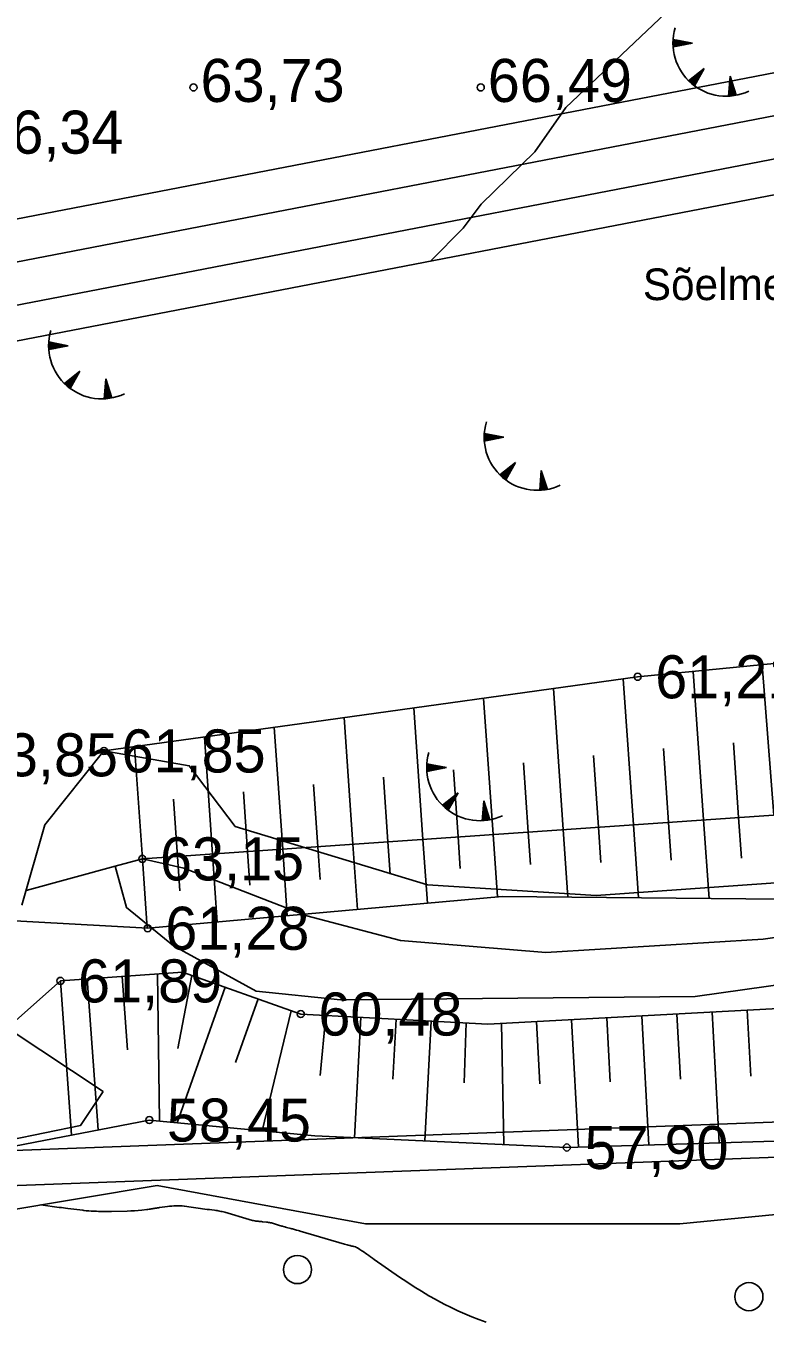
# Model space of a CAD drawing. Extents: x 532503 to 539665, y 6557663 to 6561526.
# Drawn here: x 535018.7 to 535060.8, y 6559488.9 to 6559562.5 of the extents above; entities that cross this region are included whole.
import ezdxf

# ---------------------------------------------------------------- set-up
doc = ezdxf.new("R2010")
doc.units = 0
for name, color, linetype in [('HALJASTUS', 7, 'Continuous'), ('HORISONTAAL-EH2000', 7, 'Continuous'), ('illumineerimisjooned', 7, 'Continuous'), ('kataster', 7, 'Continuous'), ('KORGUS-EH2000', 7, 'Continuous'), ('Lamami horisontaal_EH2000', 7, 'Continuous'), ('ME_aktiivne', 7, 'Continuous'), ('Plokid', 7, 'Continuous'), ('RELJEEF', 7, 'Continuous'), ('RELJEEF 1', 7, 'Continuous'), ('TM_aktiivne', 7, 'Continuous')]:
    doc.layers.add(name, color=color, linetype=linetype)

# ---------------------------------------------------------------- blocks, each defined once
blk = doc.blocks.new('TQNGER')
at = {"layer": 'RELJEEF'}
for p, q in [((-1.054, 2.309), (-0.855, 2.468)), ((-1.053, 2.374), (-0.919, 2.481)), ((-1.053, 2.245), (-0.79, 2.456)), ((-1.052, 2.183), (-0.726, 2.443)), ((-1.05, 2.44), (-0.984, 2.493)), ((-1.049, 2.121), (-0.661, 2.431)), ((0.067, 2.29), (-1.046, 2.505)), ((0.067, 2.29), (-1.045, 2.072)), ((-1.025, 2.076), (-0.597, 2.419)), ((-0.919, 2.097), (-0.532, 2.406)), ((-0.813, 2.118), (-0.468, 2.394)), ((-0.707, 2.138), (-0.404, 2.381)), ((-0.601, 2.159), (-0.339, 2.369)), ((-0.495, 2.18), (-0.275, 2.356)), ((-0.389, 2.201), (-0.21, 2.344)), ((-0.283, 2.222), (-0.146, 2.331)), ((-0.177, 2.243), (-0.081, 2.319)), ((-0.071, 2.263), (-0.017, 2.306)), ((0.731, 0.85), (-0.158, 0.146)), ((0.731, 0.85), (0.171, -0.136)), ((0.608, 0.634), (0.612, 0.756)), ((0.661, 0.728), (0.664, 0.797)), ((-0.111, 0.1), (-0.108, 0.186)), ((-0.063, 0.056), (-0.057, 0.226)), ((-0.014, 0.013), (-0.005, 0.267)), ((0.035, -0.029), (0.046, 0.308)), ((0.083, -0.068), (0.098, 0.349)), ((0.132, -0.106), (0.149, 0.389)), ((0.182, -0.117), (0.201, 0.43)), ((0.235, -0.024), (0.252, 0.471)), ((0.288, 0.07), (0.304, 0.512)), ((0.342, 0.164), (0.355, 0.553)), ((0.395, 0.258), (0.407, 0.593)), ((0.448, 0.352), (0.458, 0.634)), ((0.501, 0.446), (0.51, 0.675)), ((0.555, 0.54), (0.561, 0.716)), ((2.195, 0.402), (2.11, -0.729)), ((2.37, -0.143), (2.169, 0.055)), ((2.337, -0.04), (2.174, 0.121)), ((2.304, 0.063), (2.179, 0.186)), ((2.271, 0.166), (2.184, 0.252)), ((2.238, 0.268), (2.189, 0.317)), ((2.195, 0.402), (2.541, -0.678)), ((2.176, -0.725), (2.115, -0.665)), ((2.242, -0.72), (2.12, -0.6)), ((2.306, -0.713), (2.125, -0.534)), ((2.369, -0.705), (2.13, -0.469)), ((2.431, -0.696), (2.135, -0.403)), ((2.492, -0.686), (2.14, -0.338)), ((2.534, -0.658), (2.145, -0.272)), ((2.501, -0.555), (2.15, -0.207)), ((2.468, -0.452), (2.154, -0.141)), ((2.435, -0.349), (2.159, -0.076)), ((2.403, -0.246), (2.164, -0.01))]:
    blk.add_line(p, q, dxfattribs=at)
blk.add_arc((1.974, 2.295), 3.027, 163.42341, 295.17451, dxfattribs=at)

msp = doc.modelspace()

# ---------------------------------------------------------------- linework, layer by layer
at = {"layer": 'HALJASTUS'}
for centre in [(535034.156, 6559491.772), (535034.156, 6559491.772), (535059.835, 6559490.23), (535059.835, 6559490.23)]:
    msp.add_circle(centre, 0.8, dxfattribs=at)
at = {"layer": 'HORISONTAAL-EH2000'}
msp.add_lwpolyline([(535019.558, 6559495.452), (535020.603, 6559495.313), (535020.724, 6559495.297), (535020.844, 6559495.281), (535020.965, 6559495.265), (535021.086, 6559495.249), (535021.27, 6559495.225), (535021.438, 6559495.204), (535021.606, 6559495.183), (535021.775, 6559495.163), (535021.944, 6559495.144), (535022.002, 6559495.137), (535022.142, 6559495.123), (535022.281, 6559495.11), (535022.421, 6559495.101), (535022.561, 6559495.093), (535022.595, 6559495.092), (535022.718, 6559495.087), (535022.841, 6559495.082), (535022.964, 6559495.079), (535023.087, 6559495.077), (535023.21, 6559495.075), (535023.332, 6559495.075), (535023.455, 6559495.076), (535023.578, 6559495.079), (535024.465, 6559495.101), (535024.673, 6559495.109), (535024.881, 6559495.12), (535025.088, 6559495.137), (535025.296, 6559495.157), (535025.589, 6559495.188), (535025.649, 6559495.195), (535025.71, 6559495.203), (535025.77, 6559495.212), (535025.831, 6559495.221), (535025.892, 6559495.231), (535025.951, 6559495.241), (535026.01, 6559495.252), (535026.069, 6559495.262), (535026.127, 6559495.273), (535026.186, 6559495.283), (535026.245, 6559495.292), (535026.305, 6559495.3), (535026.766, 6559495.363), (535026.884, 6559495.377), (535027.003, 6559495.389), (535027.122, 6559495.398), (535027.242, 6559495.404), (535027.361, 6559495.405), (535027.48, 6559495.401), (535027.599, 6559495.392), (535027.717, 6559495.378), (535027.732, 6559495.375), (535027.858, 6559495.357), (535027.984, 6559495.338), (535028.11, 6559495.318), (535028.236, 6559495.298), (535028.371, 6559495.277), (535028.501, 6559495.259), (535028.63, 6559495.242), (535028.76, 6559495.227), (535028.893, 6559495.212), (535029.024, 6559495.197), (535029.155, 6559495.182), (535029.286, 6559495.167), (535029.43, 6559495.15), (535029.504, 6559495.14), (535029.578, 6559495.129), (535029.652, 6559495.116), (535029.726, 6559495.102), (535029.799, 6559495.086), (535029.872, 6559495.069), (535029.944, 6559495.05), (535030.016, 6559495.03), (535031.412, 6559494.622), (535031.474, 6559494.604), (535031.536, 6559494.588), (535031.598, 6559494.573), (535031.66, 6559494.559), (535031.723, 6559494.547), (535031.786, 6559494.536), (535031.849, 6559494.527), (535031.913, 6559494.52), (535031.98, 6559494.513), (535032.044, 6559494.507), (535032.109, 6559494.5), (535032.174, 6559494.493), (535032.397, 6559494.47), (535032.454, 6559494.463), (535032.512, 6559494.456), (535032.568, 6559494.446), (535032.625, 6559494.436), (535032.682, 6559494.424), (535032.738, 6559494.41), (535032.793, 6559494.395), (535032.849, 6559494.379), (535032.909, 6559494.361), (535032.965, 6559494.343), (535033.022, 6559494.325), (535033.079, 6559494.308), (535033.274, 6559494.246), (535033.295, 6559494.239), (535033.317, 6559494.233), (535033.338, 6559494.227), (535033.36, 6559494.22), (535033.446, 6559494.196), (535033.467, 6559494.19), (535033.489, 6559494.184), (535033.51, 6559494.179), (535033.532, 6559494.173), (535033.775, 6559494.109), (535033.827, 6559494.095), (535033.878, 6559494.081), (535033.929, 6559494.067), (535033.98, 6559494.053), (535034.037, 6559494.037), (535034.06, 6559494.03), (535034.082, 6559494.024), (535034.105, 6559494.018), (535034.128, 6559494.012), (535034.219, 6559493.987), (535034.242, 6559493.981), (535034.265, 6559493.975), (535034.288, 6559493.968), (535034.311, 6559493.962), (535036.836, 6559493.223), (535036.905, 6559493.203), (535036.973, 6559493.183), (535037.042, 6559493.164), (535037.111, 6559493.145), (535037.144, 6559493.137), (535037.197, 6559493.123), (535037.25, 6559493.109), (535037.302, 6559493.096), (535037.355, 6559493.083), (535037.461, 6559493.058), (535037.518, 6559493.034), (535037.573, 6559493.001), (535037.699, 6559492.919), (535037.822, 6559492.84), (535037.892, 6559492.797), (535038.104, 6559492.649), (535038.21, 6559492.574), (535038.315, 6559492.5), (535038.421, 6559492.426), (535038.527, 6559492.352), (535039.962, 6559491.345), (535040.372, 6559491.066), (535040.787, 6559490.794), (535041.21, 6559490.535), (535041.637, 6559490.284), (535041.749, 6559490.22), (535042.127, 6559490.011), (535042.509, 6559489.809), (535042.896, 6559489.617), (535043.286, 6559489.432), (535043.681, 6559489.257), (535044.079, 6559489.089), (535044.481, 6559488.931), (535044.886, 6559488.78)], dxfattribs=at)
at = {"layer": 'illumineerimisjooned'}
for points in [[(535103.273, 6559501.74), (534971.344, 6559496.804), (534876.945, 6559774.719), (534941.147, 6559814.604), (535178.869, 6559688.171)], [(535130.27, 6559568.319), (534960.711, 6559535.564)]]:
    msp.add_lwpolyline(points, dxfattribs=at)
at = {"layer": 'kataster'}
for points in [[(534957.01, 6559532.73), (534874.65, 6559775.26), (534941.15, 6559817.08), (535181.52, 6559689.04), (535104.64, 6559499.79), (534969.93, 6559494.75)], [(534969.93, 6559494.75), (535104.64, 6559499.79), (535276.49, 6559541.25), (535318.85, 6559280.76), (535338.01, 6559156.08), (535319.42, 6559157.12), (535277.91, 6559164.57), (535224.85, 6559174.15), (535170.96, 6559181.67), (535149.92, 6559184.62), (535125.2, 6559187.34), (535093.5, 6559192.16), (535054.28, 6559206.76)]]:
    msp.add_lwpolyline(points, close=True, dxfattribs=at)
at = {"layer": 'KORGUS-EH2000'}
for centre in [(535028.241, 6559559.043), (535044.582, 6559559.043), (535053.506, 6559525.506), (535023.148, 6559521.285), (535025.334, 6559515.144), (535025.635, 6559511.195), (535020.673, 6559508.2), (535034.345, 6559506.314), (535025.727, 6559500.282), (535049.479, 6559498.719)]:
    msp.add_circle(centre, 0.2, dxfattribs=at)
at = {"layer": 'Lamami horisontaal_EH2000'}
msp.add_lwpolyline([(535060.763, 6559568.66), (535049.425, 6559557.898), (535047.656, 6559555.377), (535044.614, 6559552.395), (535043.577, 6559551.04), (535041.734, 6559549.179)], dxfattribs=at)
at = {"layer": 'ME_aktiivne'}
msp.add_lwpolyline([(534874.54, 6559775.58), (534941.07, 6559816.91), (535181.4, 6559689.09), (535131.71, 6559566.56), (534957, 6559532.81)], close=True, dxfattribs=at)
at = {"layer": 'Plokid'}
for p, q in [((535129.606, 6559573.079), (534961.532, 6559540.611)), ((535128.53, 6559570.427), (534962.311, 6559538.317))]:
    msp.add_line(p, q, dxfattribs=at)
at = {"layer": 'RELJEEF'}
for p, q in [((535061.248, 6559517.638), (535060.586, 6559526.195)), ((535053.267, 6559517.084), (535052.69, 6559525.393)), ((535057.257, 6559517.361), (535056.67, 6559525.814)), ((535049.276, 6559516.807), (535048.719, 6559524.84)), ((535041.296, 6559516.253), (535040.776, 6559523.736)), ((535045.286, 6559516.53), (535044.747, 6559524.288)), ((535037.305, 6559515.976), (535036.805, 6559523.184)), ((535033.315, 6559515.698), (535032.833, 6559522.632)), ((535025.334, 6559515.144), (535024.891, 6559521.527)), ((535029.324, 6559515.421), (535028.862, 6559522.079)), ((535058.957, 6559521.754), (535059.252, 6559517.5)), ((535050.988, 6559521.031), (535051.272, 6559516.945)), ((535054.97, 6559521.421), (535055.262, 6559517.223)), ((535043.026, 6559520.202), (535043.291, 6559516.391)), ((535047.007, 6559520.616), (535047.281, 6559516.668)), ((535035.065, 6559519.372), (535035.31, 6559515.837)), ((535039.045, 6559519.787), (535039.3, 6559516.114)), ((535027.103, 6559518.543), (535027.329, 6559515.283)), ((535031.084, 6559518.958), (535031.32, 6559515.56)), ((535053.267, 6559517.084), (535053.556, 6559512.925)), ((535055.412, 6559515.064), (535055.262, 6559517.223)), ((535057.257, 6559517.361), (535057.568, 6559512.884)), ((535059.413, 6559515.182), (535059.252, 6559517.5)), ((535043.415, 6559514.597), (535043.291, 6559516.391)), ((535045.286, 6559516.53), (535045.532, 6559512.981)), ((535047.409, 6559514.827), (535047.281, 6559516.668)), ((535049.276, 6559516.807), (535049.543, 6559512.966)), ((535051.41, 6559514.946), (535051.272, 6559516.945)), ((535031.453, 6559513.645), (535031.32, 6559515.56)), ((535033.315, 6559515.698), (535033.578, 6559511.908)), ((535035.44, 6559513.962), (535035.31, 6559515.837)), ((535037.305, 6559515.976), (535037.563, 6559512.266)), ((535039.428, 6559514.279), (535039.3, 6559516.114)), ((535041.296, 6559516.253), (535041.548, 6559512.623)), ((535025.334, 6559515.144), (535025.608, 6559511.197)), ((535027.465, 6559513.327), (535027.329, 6559515.283)), ((535029.324, 6559515.421), (535029.593, 6559511.551)), ((535023.794, 6559514.725), (535018.719, 6559513.341)), ((535023.794, 6559514.725), (535018.719, 6559513.341)), ((535020.673, 6559508.2), (535021.3, 6559499.423)), ((535022.195, 6559508.308), (535022.809, 6559499.716)), ((535024.489, 6559504.275), (535024.19, 6559508.451)), ((535026.185, 6559508.593), (535026.301, 6559500.227)), ((535027.342, 6559504.356), (535028.149, 6559508.507)), ((535030.035, 6559507.84), (535027.305, 6559500.13)), ((535030.639, 6559503.553), (535031.92, 6559507.173)), ((535033.805, 6559506.505), (535032.147, 6559499.665)), ((535035.444, 6559502.808), (535035.77, 6559506.237)), ((535037.767, 6559506.129), (535037.397, 6559499.273)), ((535039.58, 6559502.602), (535039.765, 6559506.021)), ((535049.75, 6559505.993), (535050.138, 6559498.739)), ((535051.942, 6559502.45), (535051.747, 6559506.1)), ((535053.744, 6559506.207), (535054.137, 6559498.859)), ((535055.939, 6559502.616), (535055.742, 6559506.313)), ((535057.739, 6559506.42), (535058.136, 6559498.979)), ((535059.936, 6559502.783), (535059.736, 6559506.527)), ((535041.762, 6559505.914), (535041.393, 6559499.09)), ((535043.645, 6559502.399), (535043.759, 6559505.806)), ((535045.756, 6559505.78), (535045.896, 6559498.883)), ((535047.943, 6559502.334), (535047.753, 6559505.887))]:
    msp.add_line(p, q, dxfattribs=at)
for points in [[(535023.148, 6559521.285), (535034.404, 6559522.85), (535053.506, 6559525.506), (535069.233, 6559527.036), (535082.519, 6559528.329), (535090.413, 6559529.999), (535095.692, 6559530.063), (535108.607, 6559534.587), (535112.434, 6559540.195), (535119.19, 6559546.422), (535122.674, 6559551.274)], [(535115.71, 6559537.48), (535117.179, 6559535.9), (535119.405, 6559532.008), (535119.203, 6559528.569), (535118.652, 6559523.742), (535119.124, 6559520.895), (535118.673, 6559518.395), (535115.411, 6559514.63), (535111.925, 6559513.096), (535105.244, 6559511.435), (535101.162, 6559512.302), (535103.164, 6559517.166), (535102.041, 6559518.075), (535099.379, 6559519.632), (535096.753, 6559517.629), (535087.984, 6559515.928), (535070.199, 6559513.152), (535063.631, 6559512.823), (535045.792, 6559513.004), (535025.635, 6559511.195), (535017.019, 6559511.677)], [(535025.334, 6559515.144), (535061.775, 6559517.675), (535086.243, 6559519.901), (535098.216, 6559523.691), (535109.271, 6559527.703)], [(535018.479, 6559512.502), (535019.786, 6559517.08), (535023.148, 6559521.285)], [(535023.794, 6559514.725), (535025.334, 6559515.144)], [(535101.162, 6559512.302), (535090.131, 6559509.11), (535073.209, 6559507.246), (535058.667, 6559506.47), (535044.989, 6559505.739), (535034.345, 6559506.314), (535027.617, 6559508.696), (535020.673, 6559508.2)], [(535114.094, 6559509.719), (535109.807, 6559508.209), (535101.808, 6559506.497), (535087.906, 6559503.757), (535075.727, 6559500.637), (535065.04, 6559499.187), (535049.479, 6559498.719), (535035.148, 6559499.376), (535025.727, 6559500.282), (535016.961, 6559498.582), (535002.854, 6559496.625)], [(535010.973, 6559503.585), (535012.807, 6559504.413), (535016.06, 6559504.117), (535020.673, 6559508.2)]]:
    msp.add_lwpolyline(points, dxfattribs=at)
at = {"layer": 'RELJEEF 1'}
for points in [[(535237.204, 6559539.867), (535230.746, 6559537.601), (535224.984, 6559537.235), (535216.765, 6559538.955), (535203.132, 6559538.768), (535190.993, 6559542.132), (535177.058, 6559545.993), (535166.066, 6559546.695), (535157.327, 6559546.18), (535138.118, 6559541.535), (535127.883, 6559539.706), (535116.891, 6559534.687), (535109.271, 6559527.703), (535104.019, 6559520.041), (535094.961, 6559513.967), (535077.5, 6559510.229), (535056.77, 6559507.309), (535036.6, 6559507.123), (535031.798, 6559507.623), (535027.103, 6559510.186), (535024.435, 6559512.375), (535023.794, 6559514.725)], [(535018.479, 6559512.502), (535019.786, 6559517.08), (535023.148, 6559521.285), (535028.004, 6559520.444), (535030.618, 6559516.987), (535041.543, 6559513.67), (535051.138, 6559513.062), (535064.304, 6559513.997), (535078.427, 6559517.174), (535085.593, 6559518.785), (535092.247, 6559524.275), (535096.084, 6559528.148), (535098.378, 6559537.438)], [(535023.098, 6559501.902), (535017.755, 6559505.462), (535012.205, 6559510.392), (535009.751, 6559513.329), (535010.098, 6559518.988), (535010.951, 6559522.512), (535010.651, 6559523.907)], [(535023.794, 6559514.725), (535025.334, 6559515.144), (535027.689, 6559514.618), (535034.679, 6559511.895), (535040.015, 6559510.506), (535048.286, 6559509.812), (535060.652, 6559510.573), (535069.936, 6559511.908)], [(535002.3, 6559504.484), (535003.628, 6559501.002), (535008.964, 6559498.119), (535017.755, 6559499.133), (535021.817, 6559499.98), (535023.098, 6559501.902)], [(535017.211, 6559495.06), (535026.175, 6559496.555), (535038.034, 6559494.379), (535055.909, 6559494.379), (535062.739, 6559495.047)]]:
    msp.add_lwpolyline(points, dxfattribs=at)
at = {"layer": 'TM_aktiivne'}
msp.add_lwpolyline([(534874.54, 6559775.58), (534941.07, 6559816.91), (535181.4, 6559689.09), (535104.64, 6559499.79), (534969.93, 6559494.75)], close=True, dxfattribs=at)

# ---------------------------------------------------------------- block references
at = {"layer": 'RELJEEF'}
for p in [(535056.566, 6559559.276), (535056.566, 6559559.276), (535021.052, 6559542.054), (535045.828, 6559536.85), (535045.828, 6559536.85), (535042.56, 6559518.046), (535042.56, 6559518.046)]:
    msp.add_blockref('TQNGER', p, dxfattribs=at)

# ---------------------------------------------------------------- texts
at = {"layer": 'KORGUS-EH2000'}
for s, p in [('63,73 ', (535028.641, 6559558.218)), ('66,49 ', (535044.982, 6559558.218)), ('66,34 ', (535016.059, 6559555.274)), ('61,21 ', (535054.506, 6559524.281)), ('63,85 ', (535015.748, 6559519.84)), ('61,85 ', (535024.148, 6559520.06)), ('63,15 ', (535026.334, 6559513.919)), ('61,28 ', (535026.635, 6559509.97)), ('61,89 ', (535021.673, 6559506.975)), ('60,48 ', (535035.345, 6559505.089)), ('58,45 ', (535026.727, 6559499.057)), ('57,90 ', (535050.479, 6559497.494))]:
    msp.add_text(s, height=2.45, dxfattribs=at).set_placement(p)
at = {"layer": 'RELJEEF'}
msp.add_text('Sõelmed', height=1.8, dxfattribs=at).set_placement((535053.801, 6559546.942))

doc.saveas('drawing.dxf')
